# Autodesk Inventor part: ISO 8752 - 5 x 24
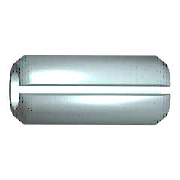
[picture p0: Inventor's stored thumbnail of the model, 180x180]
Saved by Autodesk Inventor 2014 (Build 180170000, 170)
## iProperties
IsCustomPart: 1
Company: VDW-Nachwuchsstiftung
Created: 2013-02
Part Number: ISO 8752 - 5 x 24
Material: Edelstahl, austenitisch
Description: Spannstift
Document SubType Name: Modeling
Standard: ISO 8752
Designer: e_dammj
Standards Organization: DIN
Language: de-DE
Size Designation: 5 x 24
Categories: <MemberInstance><Categories><Category DisplayName="Verbindungselemente" InternalName="e4da775c-781d-43d5-af7c-5136215cf5a6" Mnemonic="FSTN"><Category DisplayNam
Density: 8.03 g/cm^3
Appearance: Halbpoliert
Author: e_dammj
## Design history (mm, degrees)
sketch "Skizze1"
  geometry: L1 (0, 1.8)-(0, 2.559); L2 (0, 2.559)-(0.9, 2.8); L3 (0.9, 2.8)-(23.1, 2.8); L4 (23.1, 2.8)-(24, 2.559); L5 (24, 2.559)-(24, 1.8); L6 (24, 0)-(0, 0); L7 (0, 1.8)-(24, 1.8); L8 (0, 1.8)-(0, 0); L9 (24, 1.8)-(24, 0); L10 (0, 1.68)-(0, -0.28) reference; L11 (-2, 0)-(12, 0) reference
  constraints: 18 end point, 3 parallel, 3 perpendicular, 1 coincident, 1 point on line, 1 vertical
  dimensions: "d0" = 24 distance between parallel lines of L5 L1 (= NLG); "d1" = 5.6 diameter of L3 L6 (= NND1); "d2" = 3.6 diameter of L7 L6 (= NND1 - 2 x SD); "d3" = 15 deg angle of L3 L2 (= FAWI); "d4" = 15 deg angle of L4 L3 (= FAWI); "d7" = 0.24115 vertical distance of L2.end L1.end (computed from SD, FAWI, PHH); "d8" = 0.24115 vertical distance of L3.end L4.end (computed from SD, FAWI, PHH1)
revolve "Körper" sketch "Skizze1" stored, may be unused: angle "d10" = 90 deg
workplane "Work Plane1"
sketch "Skizze2"
  geometry: L1 (-0.226, 1.786)-(-0.351, 2.778); L2 (0.226, 1.786)-(0.351, 2.778); L3 (0, 1.68)-(0, -0.28) reference; L4 (-0.246, 0)-(0.246, 0) reference; A1 r 2.8 centre (0, 0) between (0.351, 2.778) and (-0.351, 2.778); A2 r 1.8 centre (0, 0) between (0.226, 1.786) and (-0.226, 1.786); 1 further point
  constraints: 4 end point, 4 point on circle, 2 centre point, 2 coincident, 2 horizontal alignment, 1 other
  dimensions: "d11" = 2.8 radius of A1 (= 0.5 x NND1); "d12" = 1.8 radius of A2 (= -SD + 0.5 x NND1); "d14" = 1 distance of L1.start L1.end (= SD); "d15" = 7.2 deg angle of L3 L1
extrude "Schnitt" cut sketch "Skizze2" stored distance "d5" = 24 (= NLG); taper "d6" = 0 deg
body "Solid1"
other parameters: "NND" = 5 [user parameter], "NLG" = 24 [user parameter; used in 3 equation terms], "SD" = 1 [user parameter; used in 5 equation terms], "PHH" = 0.9 [user parameter; used in 2 equation terms], "PHH1" = 0.9 (= PHH) [user parameter; used in 1 equation term], "FAWI" = 15 deg [user parameter; used in 4 equation terms], "d9" = 12 (= 0.5 x NLG), "d31" = 0, "d32" = 0, "d33" = 0, "NND1" = 5.6 [user parameter; used in 4 equation terms]
